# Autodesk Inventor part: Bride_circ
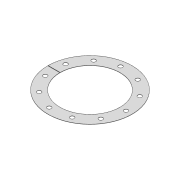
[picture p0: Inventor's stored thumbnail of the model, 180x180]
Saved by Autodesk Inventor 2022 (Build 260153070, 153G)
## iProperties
Created: 2021-07
Part Number: Bride_circ
Material: Générique
Document SubType Name: Sheet Metal
Designer: Fabian
Density: 1 g/cm^3
Flat Pattern Width: 21 cm
Flat Pattern Length: 20.9999 cm
Flat Pattern Area: 440.997 cm^2
Sheet Metal Rule: Par défaut_mm
Sheet Metal Width: 210,000 mm
Sheet Metal Length: 209,999 mm
Sheet Metal Area: 44099,750 mm^2
Appearance: Par défaut
Author: Fabian
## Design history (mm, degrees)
derived "Tremie.ipt"
sketch "Esquisse1"
  geometry: A1 r 105 centre (104.999, 0.5) between (0, 0) and (0, 1); A2 r 75 centre (104.999, 0.5) between (30, 0) and (30, 1) reference; 2 further points
  constraints: 2 coincident, 2 horizontal alignment, 2 point on circle, 1 centre point, 2 other
  dimensions: "d4" = 30 radial gap between concentric circles of A2 A1 (derived); "d6" = 15 dimension on A1 (= 0.5 x d4)
hole "Perçage1" sketch "Esquisse1" at (194.999, 0.5) diameter "d7" = 10; stored, may be unused: countersink angle "d11" = 90 deg, drill point angle "d13" = 118 deg; dims "d8" = 6, "d9" = 4, "d10" = 2, "d12" = 0.5 (= Epaisseur)
pattern_circular "Réseau circulaire1" dims angle "d15" = 360 deg
feature "Bride_circ::Tremie.ipt" dims "d0" = 10
tag "FonctionRepérage1"
node "Solide1"
feature "Définition1"
other parameters: "Epaisseur" = 0.5 (derived), "RayonPli" = 0.5 (= Epaisseur), "LargeurGrugeage" = 0.5 (= Epaisseur), "ProfondeurGrugeage" = 0.25 (= 0.5 x Epaisseur), "TailleGrugeage" = 2 (= 4 x Epaisseur), "SeamGap" = 0.01, "RestesMinimum" = 1 (= 2 x Epaisseur), "Rayondetransition" = 0.5 (= RayonPli), "TailleRayonJacobi" = 0.5 (= RayonPli), "TailleJeu" = 0.5 (= Epaisseur), "d1" = 0.5 (= Epaisseur), "Epaisseur" = 0.5, "LargeurGrugeage" = 0.5, "ProfondeurGrugeage" = 0.25, "RayonPli" = 0.5, "Rayondetransition" = 0.5, "RestesMinimum" = 1, "TailleGrugeage" = 2, "TailleJeu" = 0.5, "TailleRayonJacobi" = 0.5
